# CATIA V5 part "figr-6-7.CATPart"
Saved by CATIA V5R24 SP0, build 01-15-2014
Part number: Part1
Bounding box of the stored display mesh (mm): x -62.5 to 62.5, y -75 to 75, z 0 to 20
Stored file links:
  D:\KAVITA\CATIA V5-6R2014 Project_ Kavita\CATIA V5-6R2014_partfiles\Partfiles\c06_catia_v5-6r2014_prt\figr-6-7.CATPart
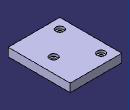
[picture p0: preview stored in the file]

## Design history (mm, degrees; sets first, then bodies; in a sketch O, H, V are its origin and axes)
Body1 (main body)
  Sketch1 on xy-plane, origin (0, 0, 0), H (1, 0, 0), V (0, 1, 0)
    line L1 (-62.5, 75) -> (62.5, 75)
    line L2 (62.5, 75) -> (62.5, -75)
    line L3 (62.5, -75) -> (-62.5, -75)
    line L4 (-62.5, -75) -> (-62.5, 75)
    axis line L5 (62.5, -75) -> (-62.5, 75)
    length L2 = 150
    length L3 = 125
    horizontal: L1 H, L3 H
    vertical: L2 V, L4 V
    midpoint: O L5
  Pad1: profile Sketch1, direction (0, 0, 1), length 20
  Sketch2 on face of Pad1, origin (-40.5285, -55.3052, 20), H (1, 0, 0), V (0, 1, 0)
    point P1 (3.0285, 5.3052)
    reference projected line E1 (-21.9715, -19.6948) -> (103.0285, -19.6948) from edge [face of Pad1 | face of Pad1]
    reference projected line E2 (-21.9715, 130.3052) -> (-21.9715, -19.6948) from edge [face of Pad1 | face of Pad1]
    distance P1 E1 = 25
    distance P1 E2 = 25
  Hole1: placed by Sketch2, at (-37.5, -50, 20) direction (0, 0, -1), diameter 11, through (limit type 3), counterbore diameter 19, counterbore depth 6
  Sketch3 on face of Pad1, origin (-46.6283, 59.6815, 20), H (1, 0, 0), V (0, 1, 0)
    point P1 (9.1283, -9.6815)
    reference projected line E1 (-15.8717, 15.3185) -> (-15.8717, -134.6815) from edge [face of Pad1 | face of Pad1]
    reference projected line E2 (109.1283, 15.3185) -> (-15.8717, 15.3185) from edge [face of Pad1 | face of Pad1]
    distance P1 E1 = 25
    distance P1 E2 = 25
  Hole2: placed by Sketch3, at (-37.5, 50, 20) direction (0, 0, -1), diameter 11, through (limit type 3), counterbore diameter 19, counterbore depth 6
  Sketch4 on face of Pad1, origin (29.7716, -8.2192, 20), H (1, 0, 0), V (0, 1, 0)
    point P1 (-2.2716, 8.2192)
    reference projected line E1 (-92.2716, -66.7808) -> (32.7284, -66.7808) from edge [face of Pad1 | face of Pad1]
    reference projected line E2 (32.7284, -66.7808) -> (32.7284, 83.2192) from edge [face of Pad1 | face of Pad1]
    distance P1 E1 = 75
    distance P1 E2 = 35
  Hole3: placed by Sketch4, at (27.5, 0, 20) direction (0, 0, -1), diameter 11, through (limit type 3), counterbore diameter 19, counterbore depth 6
